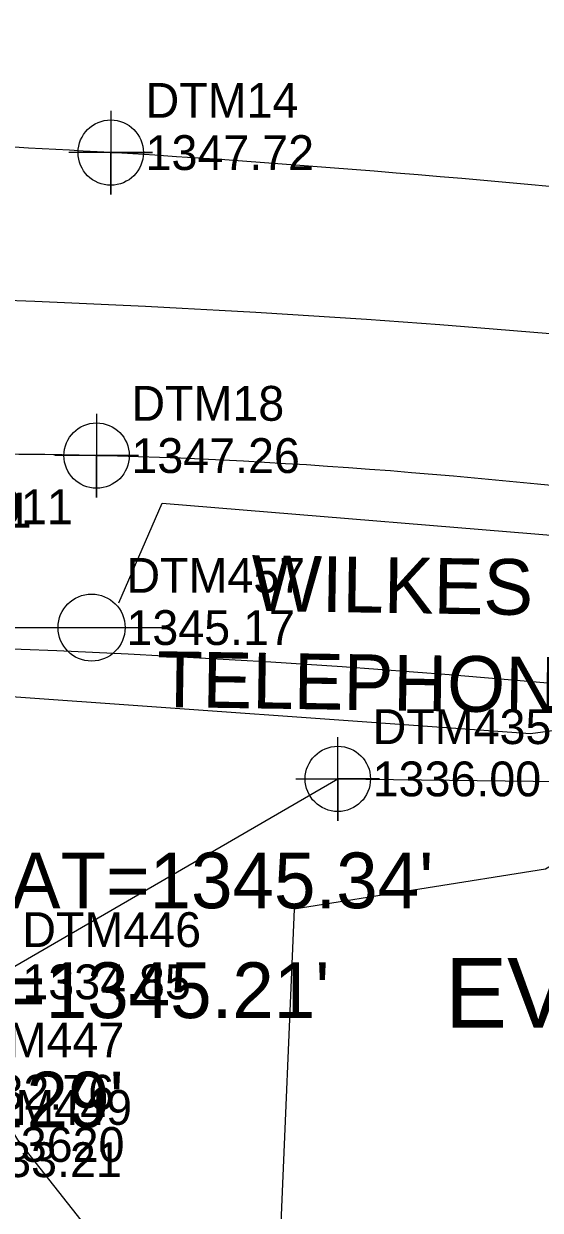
# Model space of a CAD drawing. Extents: x 1303760 to 1305114, y 904598 to 905144.
# Drawn here: x 1304402.5 to 1304439.6, y 904750.7 to 904835.9 of the extents above; entities that cross this region are included whole.
import ezdxf

# ---------------------------------------------------------------- set-up
doc = ezdxf.new("R2010")
doc.units = 0
for name, color, linetype in [('Exist Horizontal Alignment', 7, 'Continuous'), ('Exist Hydro Jurisdictional Stream or Body of Water', 7, 'Continuous'), ('Exist Hydro Stream or Body of Water Cogo Comment', 7, 'Continuous'), ('Exist Hydro Stream or Body of Water Cogo Elevation', 7, 'Continuous'), ('Exist Hydro Stream or Body of Water Cogo Number', 7, 'Continuous'), ('Exist Hydro Stream or Body of Water Cogo Point CELL', 7, 'Continuous'), ('Exist Property Owner Text', 7, 'Continuous'), ('Exist Right of Way Line', 7, 'Continuous'), ('Exist Roads EOP', 7, 'Continuous'), ('Exist Roads EOP Cogo Comment', 7, 'Continuous'), ('Exist Roads EOP Cogo Elevation', 7, 'Continuous'), ('Exist Roads EOP Cogo Number', 7, 'Continuous'), ('Exist Roads EOP Cogo Point CELL', 7, 'Continuous'), ('Exist Structure Major Bridge Seat Top Elevation', 7, 'Continuous'), ('Exist Utilities Telephone Pole CELL', 7, 'Continuous'), ('Exist Utilities Telephone Pole Cogo Elevation', 7, 'Continuous'), ('Exist Utilities Telephone Pole Cogo Number', 7, 'Continuous'), ('Exist Utilities Telephone Pole Text', 7, 'Continuous'), ('Exist Utilities Telephone UG FO', 7, 'Continuous'), ('Exist Vegetation Woods Line', 7, 'Continuous'), ('Old_Level_20', 7, 'Continuous')]:
    doc.layers.add(name, color=color, linetype=linetype)

msp = doc.modelspace()

# ---------------------------------------------------------------- linework, layer by layer
at = {"layer": 'Exist Horizontal Alignment'}
msp.add_arc((1304372.368, 904026.264), 790.287, 76.439473, 88.713275, dxfattribs=at)
at = {"layer": 'Exist Hydro Jurisdictional Stream or Body of Water'}
msp.add_lwpolyline([(1304394.442, 904759.176), (1304399.943, 904767.101), (1304425.072, 904781.673), (1304461.071, 904781.237), (1304501.307, 904778.746), (1304516.441, 904777.489), (1304521.111, 904783.208)], dxfattribs=at)
at = {"layer": 'Exist Hydro Stream or Body of Water Cogo Point CELL'}
for points in [[(1304422.072, 904781.673), (1304428.072, 904781.673), (1304425.072, 904781.673), (1304425.072, 904778.673), (1304425.072, 904784.673)], [(1304396.943, 904767.101), (1304402.943, 904767.101), (1304399.943, 904767.101), (1304399.943, 904764.101), (1304399.943, 904770.101)]]:
    msp.add_lwpolyline(points, dxfattribs=at)
msp.add_circle((1304425.072, 904781.673), 2.344, dxfattribs=at)
at = {"layer": 'Exist Right of Way Line'}
for radius in [815.287, 765.287]:
    msp.add_arc((1304372.368, 904026.264), radius, 76.439473, 88.713275, dxfattribs=at)
at = {"layer": 'Exist Roads EOP'}
for points in [[(1304576.045, 904800.977), (1304538.546, 904810.643), (1304508.702, 904816.011), (1304459.119, 904822.305), (1304408.784, 904826.64), (1304377.251, 904828.079)], [(1304562.244, 904782.526), (1304533.367, 904789.049), (1304505.015, 904793.929), (1304455.887, 904800.991), (1304407.768, 904804.887), (1304387.953, 904804.961)]]:
    msp.add_spline(points, degree=3, dxfattribs=at)
at = {"layer": 'Exist Roads EOP Cogo Point CELL'}
for points in [[(1304408.784, 904829.64), (1304408.784, 904823.64), (1304408.784, 904826.64), (1304411.784, 904826.64), (1304405.784, 904826.64)], [(1304407.768, 904807.887), (1304407.768, 904801.887), (1304407.768, 904804.887), (1304410.768, 904804.887), (1304404.768, 904804.887)]]:
    msp.add_lwpolyline(points, dxfattribs=at)
for centre in [(1304408.784, 904826.64), (1304407.768, 904804.887)]:
    msp.add_circle(centre, 2.344, dxfattribs=at)
at = {"layer": 'Exist Utilities Telephone Pole CELL'}
for p, q in [((1304401.735, 904792.538), (1304413.073, 904792.538)), ((1304407.41, 904792.538), (1304407.41, 904792.538))]:
    msp.add_line(p, q, dxfattribs=at)
msp.add_circle((1304407.41, 904792.538), 2.407, dxfattribs=at)
at = {"layer": 'Exist Utilities Telephone UG FO'}
msp.add_lwpolyline([(1304409.355, 904794.324), (1304412.475, 904801.464), (1304445.014, 904798.786), (1304505.189, 904790.308)], dxfattribs=at)
at = {"layer": 'Exist Vegetation Woods Line'}
msp.add_lwpolyline([(1304426.164, 904725.224), (1304402.128, 904755.751), (1304398.899, 904761.139), (1304366.252, 904790.588), (1304399.975, 904787.715), (1304438.9, 904784.945), (1304461.091, 904787.92), (1304439.976, 904775.196), (1304421.936, 904772.323), (1304420.911, 904748.107), (1304445.306, 904738.256), (1304463.077, 904728.534), (1304471.892, 904719.504), (1304474.557, 904695.082), (1304476.249, 904686.719), (1304487.011, 904673.072)], dxfattribs=at)
at = {"layer": 'Old_Level_20'}
msp.add_arc((1304372.368, 904026.264), 790.287, 76.439473, 88.713275, dxfattribs=at)

# ---------------------------------------------------------------- texts
at = {"layer": 'Exist Hydro Stream or Body of Water Cogo Comment'}
msp.add_text('*EL3620', height=2.5, dxfattribs=at).set_placement((1304396.942, 904754.176))
at = {"layer": 'Exist Hydro Stream or Body of Water Cogo Elevation'}
for s, p in [('1336.00', (1304427.572, 904780.423)), ('1334.85', (1304402.443, 904765.851)), ('1332.76', (1304396.942, 904757.926)), ('1333.21', (1304397.493, 904753.083))]:
    msp.add_text(s, height=2.5, dxfattribs=at).set_placement(p)
at = {"layer": 'Exist Hydro Stream or Body of Water Cogo Number'}
for s, p in [('DTM435', (1304427.572, 904784.173)), ('DTM446', (1304402.443, 904769.601)), ('DTM447', (1304396.942, 904761.676)), ('DTM449', (1304397.493, 904756.833))]:
    msp.add_text(s, height=2.5, dxfattribs=at).set_placement(p)
at = {"layer": 'Exist Property Owner Text'}
msp.add_text('EVELYN S. VINSON', height=5, dxfattribs=at).set_placement((1304432.756, 904763.811))
at = {"layer": 'Exist Roads EOP Cogo Comment'}
for s, p in [('*EL30011', (1304388.433, 904799.717)), ('*OC30011', (1304390.453, 904799.961))]:
    msp.add_text(s, height=2.5, dxfattribs=at).set_placement(p)
at = {"layer": 'Exist Roads EOP Cogo Elevation'}
for s, p in [('1347.72', (1304411.284, 904825.39)), ('1347.26', (1304410.268, 904803.637))]:
    msp.add_text(s, height=2.5, dxfattribs=at).set_placement(p)
at = {"layer": 'Exist Roads EOP Cogo Number'}
for s, p in [('DTM14', (1304411.284, 904829.14)), ('DTM18', (1304410.268, 904807.387))]:
    msp.add_text(s, height=2.5, dxfattribs=at).set_placement(p)
at = {"layer": 'Exist Structure Major Bridge Seat Top Elevation'}
for s, p in [("SEAT=1345.34'", (1304394.477, 904772.386)), ("SEAT=1345.21'", (1304387.025, 904764.5)), ("SEAT=1345.29'", (1304372.268, 904756.647))]:
    msp.add_text(s, height=4, dxfattribs=at).set_placement(p)
at = {"layer": 'Exist Utilities Telephone Pole Cogo Elevation'}
msp.add_text('1345.17', height=2.5, dxfattribs=at).set_placement((1304409.91, 904791.288))
at = {"layer": 'Exist Utilities Telephone Pole Cogo Number'}
msp.add_text('DTM457', height=2.5, dxfattribs=at).set_placement((1304409.91, 904795.038))
at = {"layer": 'Exist Utilities Telephone Pole Text'}
for s, p in [('WILKES ', (1304418.845, 904793.741)), ('TELEPHONE', (1304412.077, 904786.843))]:
    msp.add_text(s, height=4, rotation=359.12595, dxfattribs=at).set_placement(p)

doc.saveas('drawing.dxf')
